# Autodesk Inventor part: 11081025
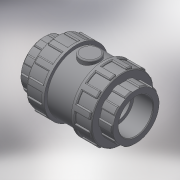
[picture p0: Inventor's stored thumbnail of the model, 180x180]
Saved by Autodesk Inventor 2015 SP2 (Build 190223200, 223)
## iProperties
Created: 2017-11
Part Number: 11081025
Material: Generic
Description: PLASSON CHECK VALVE THR 2 1/2" PTFE COATED SPRING + EPDM O-RING
Document SubType Name: Modeling
Designer: KIM
Density: 1 g/cm^3
Appearance: Default
Author: KIM
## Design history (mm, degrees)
derived "110810 - 110610 110910 - 110010.ipt"
feature "Solid1::110810 - 110610 110910 - 110010.ipt"
tag "TaggingFeature1"
body "Solid1"
other parameters: "d0" = 215, "d1" = 72.226, "d2" = 139, "d3" = 44, "d4" = 57.7808, "d5" = 30.8, "d7" = 101.1164, "d8" = 125.1, "d13" = 2.16678, "d23" = 44, "d24" = 133.44, "d25" = 1.44452, "d26" = 2.16678, "d27" = 20.85, "d28" = 10.425, "d29" = 33, "d30" = 0, "d35" = 2.16678, "d39" = 69.5, "d45" = 360 deg, "d47" = 1.44452, "d50" = 69.5, "d51" = 41.7, "d53" = 0, "d54" = 2.78, "d55" = 14.4452, "d56" = 7.2226, "d58" = 0, "d59" = 2.16678, "d61" = 360 deg, "G_" = 72.226, "l_" = 44, "H_" = 215, "K_" = 139
